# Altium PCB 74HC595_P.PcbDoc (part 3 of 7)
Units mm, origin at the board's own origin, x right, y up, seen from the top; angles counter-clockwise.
Board outline 89.11 x 89.03 mm, 2 copper layers (Top Layer, Bottom Layer); 552 components, 23 nets, 1488 pads, 408 vias.
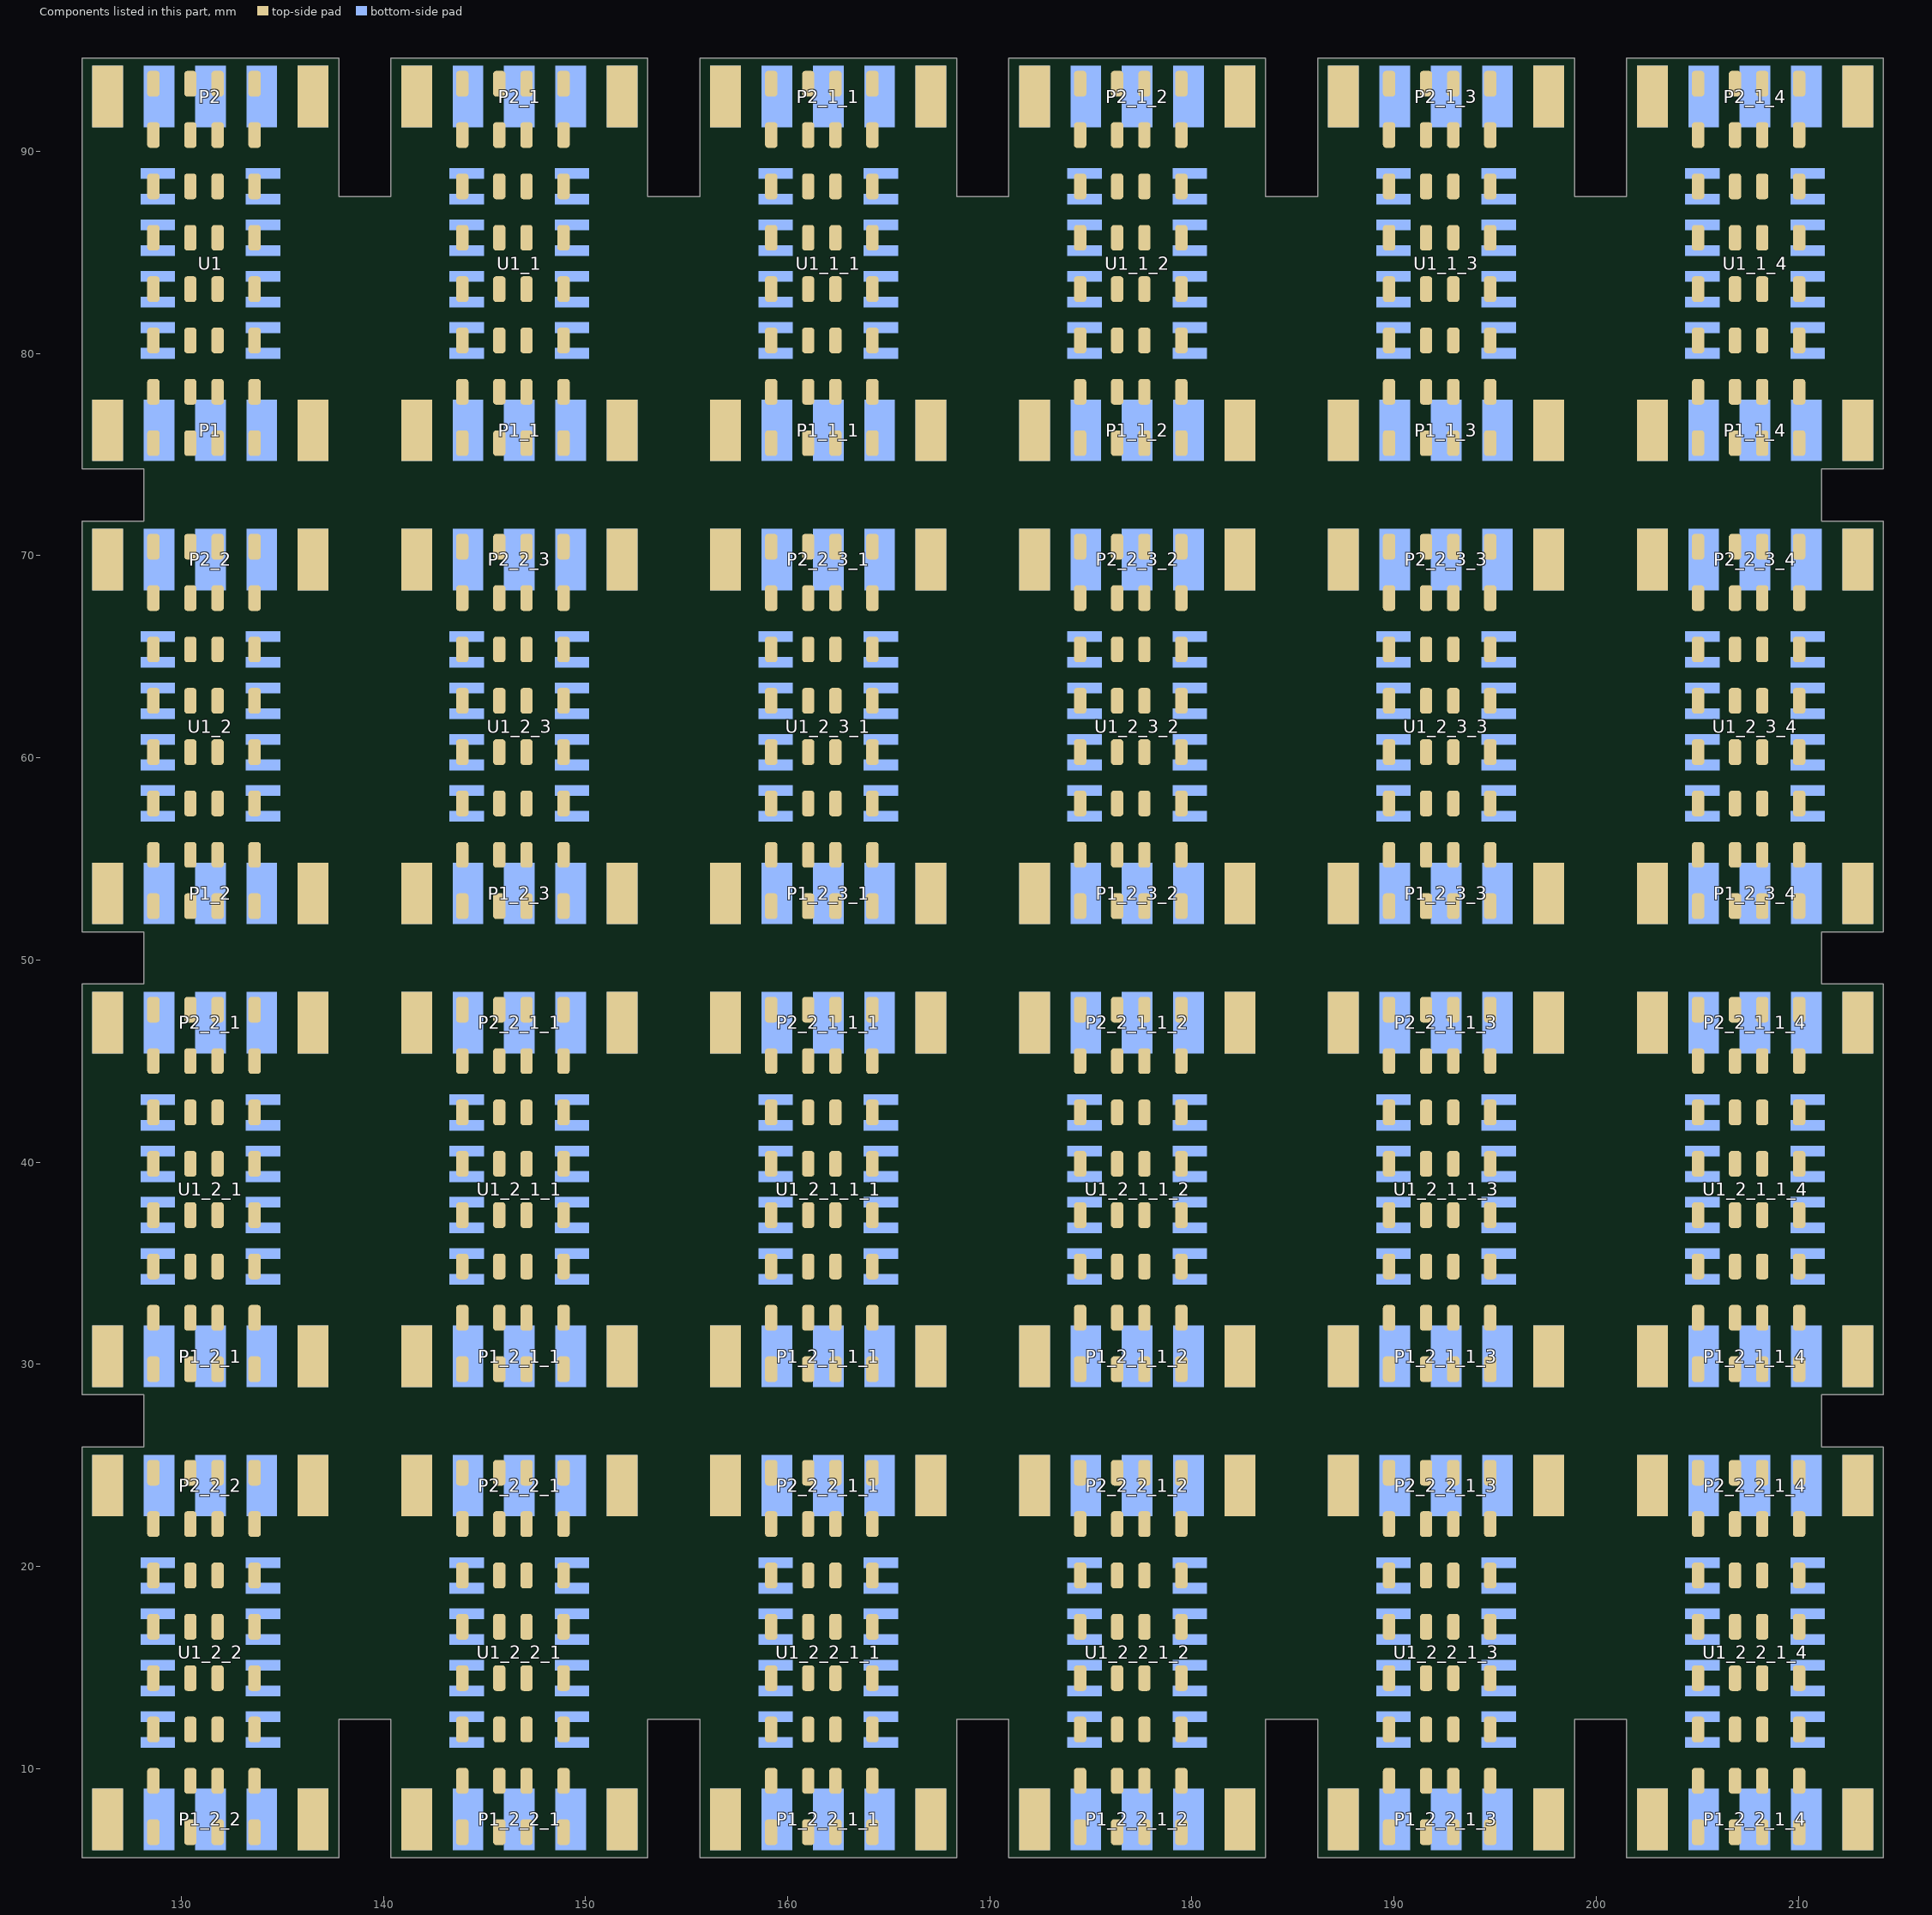
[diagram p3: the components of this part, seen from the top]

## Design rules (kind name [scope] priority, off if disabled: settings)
Clearance [All] p1: gap=0.254
PolygonConnect [All] p1: connectstyle=Relief reliefconductorwidth=0.254 reliefentries=4 polygonreliefangle="90 Angle" airgapwidth=0.254
RoutingVias [All] p1: holewidth=0.381 width=0.635 viastyle="Through Hole" minholewidth=0.254 minwidth=0.381 maxholewidth=1.27 maxwidth=1.524
SolderMaskExpansion [All] p1: expansion=0.102
Width [All] p1: maxlimit=1.27 minlimit=0.254 preferedwidth=0.381
30 further rules are at their usual default settings.

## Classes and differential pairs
component class EspPov: D1 D2 D3 D4 D5 D6 D7 D8 P1 P2 P3 P4 P5 P6 R1 R2 R3 R4 R5 R6 R7 R8 U1

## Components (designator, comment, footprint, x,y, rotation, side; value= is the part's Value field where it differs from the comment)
D1 "color?" LED_0805_RED 132.715,75.565 r180 top
D1_1 "color?" LED_0805_RED 147.997,75.565 r180 top (schematic designator D1)
D1_1_1 "color?" LED_0805_RED 163.279,75.565 r180 top (schematic designator D1)
D1_1_2 "color?" LED_0805_RED 178.561,75.565 r180 top (schematic designator D1)
D1_1_3 "color?" LED_0805_RED 193.843,75.565 r180 top (schematic designator D1)
D1_1_4 "color?" LED_0805_RED 209.125,75.565 r180 top (schematic designator D1)
D1_2 "color?" LED_0805_RED 132.715,52.663 r180 top (schematic designator D1)
D1_2_1 "color?" LED_0805_RED 132.715,29.761 r180 top (schematic designator D1)
D1_2_1_1 "color?" LED_0805_RED 147.997,29.761 r180 top (schematic designator D1)
D1_2_1_1_1 "color?" LED_0805_RED 163.279,29.761 r180 top (schematic designator D1)
D1_2_1_1_2 "color?" LED_0805_RED 178.561,29.761 r180 top (schematic designator D1)
D1_2_1_1_3 "color?" LED_0805_RED 193.843,29.761 r180 top (schematic designator D1)
D1_2_1_1_4 "color?" LED_0805_RED 209.125,29.761 r180 top (schematic designator D1)
D1_2_2 "color?" LED_0805_RED 132.715,6.859 r180 top (schematic designator D1)
D1_2_2_1 "color?" LED_0805_RED 147.997,6.859 r180 top (schematic designator D1)
D1_2_2_1_1 "color?" LED_0805_RED 163.279,6.859 r180 top (schematic designator D1)
D1_2_2_1_2 "color?" LED_0805_RED 178.561,6.859 r180 top (schematic designator D1)
D1_2_2_1_3 "color?" LED_0805_RED 193.843,6.859 r180 top (schematic designator D1)
D1_2_2_1_4 "color?" LED_0805_RED 209.125,6.859 r180 top (schematic designator D1)
D1_2_3 "color?" LED_0805_RED 147.997,52.663 r180 top (schematic designator D1)
D1_2_3_1 "color?" LED_0805_RED 163.279,52.663 r180 top (schematic designator D1)
D1_2_3_2 "color?" LED_0805_RED 178.561,52.663 r180 top (schematic designator D1)
D1_2_3_3 "color?" LED_0805_RED 193.843,52.663 r180 top (schematic designator D1)
D1_2_3_4 "color?" LED_0805_RED 209.125,52.663 r180 top (schematic designator D1)
D2 "color?" LED_0805_RED 132.715,78.105 r180 top
D2_1 "color?" LED_0805_RED 147.997,78.105 r180 top (schematic designator D2)
D2_1_1 "color?" LED_0805_RED 163.279,78.105 r180 top (schematic designator D2)
D2_1_2 "color?" LED_0805_RED 178.561,78.105 r180 top (schematic designator D2)
D2_1_3 "color?" LED_0805_RED 193.843,78.105 r180 top (schematic designator D2)
D2_1_4 "color?" LED_0805_RED 209.125,78.105 r180 top (schematic designator D2)
D2_2 "color?" LED_0805_RED 132.715,55.203 r180 top (schematic designator D2)
D2_2_1 "color?" LED_0805_RED 132.715,32.301 r180 top (schematic designator D2)
D2_2_1_1 "color?" LED_0805_RED 147.997,32.301 r180 top (schematic designator D2)
D2_2_1_1_1 "color?" LED_0805_RED 163.279,32.301 r180 top (schematic designator D2)
D2_2_1_1_2 "color?" LED_0805_RED 178.561,32.301 r180 top (schematic designator D2)
D2_2_1_1_3 "color?" LED_0805_RED 193.843,32.301 r180 top (schematic designator D2)
D2_2_1_1_4 "color?" LED_0805_RED 209.125,32.301 r180 top (schematic designator D2)
D2_2_2 "color?" LED_0805_RED 132.715,9.399 r180 top (schematic designator D2)
D2_2_2_1 "color?" LED_0805_RED 147.997,9.399 r180 top (schematic designator D2)
D2_2_2_1_1 "color?" LED_0805_RED 163.279,9.399 r180 top (schematic designator D2)
D2_2_2_1_2 "color?" LED_0805_RED 178.561,9.399 r180 top (schematic designator D2)
D2_2_2_1_3 "color?" LED_0805_RED 193.843,9.399 r180 top (schematic designator D2)
D2_2_2_1_4 "color?" LED_0805_RED 209.125,9.399 r180 top (schematic designator D2)
D2_2_3 "color?" LED_0805_RED 147.997,55.203 r180 top (schematic designator D2)
D2_2_3_1 "color?" LED_0805_RED 163.279,55.203 r180 top (schematic designator D2)
D2_2_3_2 "color?" LED_0805_RED 178.561,55.203 r180 top (schematic designator D2)
D2_2_3_3 "color?" LED_0805_RED 193.843,55.203 r180 top (schematic designator D2)
D2_2_3_4 "color?" LED_0805_RED 209.125,55.203 r180 top (schematic designator D2)
D3 "color?" LED_0805_RED 132.715,80.645 r180 top
D3_1 "color?" LED_0805_RED 147.997,80.645 r180 top (schematic designator D3)
D3_1_1 "color?" LED_0805_RED 163.279,80.645 r180 top (schematic designator D3)
D3_1_2 "color?" LED_0805_RED 178.561,80.645 r180 top (schematic designator D3)
D3_1_3 "color?" LED_0805_RED 193.843,80.645 r180 top (schematic designator D3)
D3_1_4 "color?" LED_0805_RED 209.125,80.645 r180 top (schematic designator D3)
D3_2 "color?" LED_0805_RED 132.715,57.743 r180 top (schematic designator D3)
D3_2_1 "color?" LED_0805_RED 132.715,34.841 r180 top (schematic designator D3)
D3_2_1_1 "color?" LED_0805_RED 147.997,34.841 r180 top (schematic designator D3)
D3_2_1_1_1 "color?" LED_0805_RED 163.279,34.841 r180 top (schematic designator D3)
D3_2_1_1_2 "color?" LED_0805_RED 178.561,34.841 r180 top (schematic designator D3)
D3_2_1_1_3 "color?" LED_0805_RED 193.843,34.841 r180 top (schematic designator D3)
D3_2_1_1_4 "color?" LED_0805_RED 209.125,34.841 r180 top (schematic designator D3)
D3_2_2 "color?" LED_0805_RED 132.715,11.939 r180 top (schematic designator D3)
D3_2_2_1 "color?" LED_0805_RED 147.997,11.939 r180 top (schematic designator D3)
D3_2_2_1_1 "color?" LED_0805_RED 163.279,11.939 r180 top (schematic designator D3)
D3_2_2_1_2 "color?" LED_0805_RED 178.561,11.939 r180 top (schematic designator D3)
D3_2_2_1_3 "color?" LED_0805_RED 193.843,11.939 r180 top (schematic designator D3)
D3_2_2_1_4 "color?" LED_0805_RED 209.125,11.939 r180 top (schematic designator D3)
D3_2_3 "color?" LED_0805_RED 147.997,57.743 r180 top (schematic designator D3)
D3_2_3_1 "color?" LED_0805_RED 163.279,57.743 r180 top (schematic designator D3)
D3_2_3_2 "color?" LED_0805_RED 178.561,57.743 r180 top (schematic designator D3)
D3_2_3_3 "color?" LED_0805_RED 193.843,57.743 r180 top (schematic designator D3)
D3_2_3_4 "color?" LED_0805_RED 209.125,57.743 r180 top (schematic designator D3)
D4 "color?" LED_0805_RED 132.715,83.185 r180 top
D4_1 "color?" LED_0805_RED 147.997,83.185 r180 top (schematic designator D4)
D4_1_1 "color?" LED_0805_RED 163.279,83.185 r180 top (schematic designator D4)
D4_1_2 "color?" LED_0805_RED 178.561,83.185 r180 top (schematic designator D4)
D4_1_3 "color?" LED_0805_RED 193.843,83.185 r180 top (schematic designator D4)
D4_1_4 "color?" LED_0805_RED 209.125,83.185 r180 top (schematic designator D4)
D4_2 "color?" LED_0805_RED 132.715,60.283 r180 top (schematic designator D4)
D4_2_1 "color?" LED_0805_RED 132.715,37.381 r180 top (schematic designator D4)
D4_2_1_1 "color?" LED_0805_RED 147.997,37.381 r180 top (schematic designator D4)
D4_2_1_1_1 "color?" LED_0805_RED 163.279,37.381 r180 top (schematic designator D4)
D4_2_1_1_2 "color?" LED_0805_RED 178.561,37.381 r180 top (schematic designator D4)
D4_2_1_1_3 "color?" LED_0805_RED 193.843,37.381 r180 top (schematic designator D4)
D4_2_1_1_4 "color?" LED_0805_RED 209.125,37.381 r180 top (schematic designator D4)
D4_2_2 "color?" LED_0805_RED 132.715,14.479 r180 top (schematic designator D4)
D4_2_2_1 "color?" LED_0805_RED 147.997,14.479 r180 top (schematic designator D4)
D4_2_2_1_1 "color?" LED_0805_RED 163.279,14.479 r180 top (schematic designator D4)
D4_2_2_1_2 "color?" LED_0805_RED 178.561,14.479 r180 top (schematic designator D4)
D4_2_2_1_3 "color?" LED_0805_RED 193.843,14.479 r180 top (schematic designator D4)
D4_2_2_1_4 "color?" LED_0805_RED 209.125,14.479 r180 top (schematic designator D4)
D4_2_3 "color?" LED_0805_RED 147.997,60.283 r180 top (schematic designator D4)
D4_2_3_1 "color?" LED_0805_RED 163.279,60.283 r180 top (schematic designator D4)
D4_2_3_2 "color?" LED_0805_RED 178.561,60.283 r180 top (schematic designator D4)
D4_2_3_3 "color?" LED_0805_RED 193.843,60.283 r180 top (schematic designator D4)
D4_2_3_4 "color?" LED_0805_RED 209.125,60.283 r180 top (schematic designator D4)
D5 "color?" LED_0805_RED 132.715,85.725 r180 top
D5_1 "color?" LED_0805_RED 147.997,85.725 r180 top (schematic designator D5)
D5_1_1 "color?" LED_0805_RED 163.279,85.725 r180 top (schematic designator D5)
D5_1_2 "color?" LED_0805_RED 178.561,85.725 r180 top (schematic designator D5)
D5_1_3 "color?" LED_0805_RED 193.843,85.725 r180 top (schematic designator D5)
D5_1_4 "color?" LED_0805_RED 209.125,85.725 r180 top (schematic designator D5)
D5_2 "color?" LED_0805_RED 132.715,62.823 r180 top (schematic designator D5)
D5_2_1 "color?" LED_0805_RED 132.715,39.921 r180 top (schematic designator D5)
D5_2_1_1 "color?" LED_0805_RED 147.997,39.921 r180 top (schematic designator D5)
D5_2_1_1_1 "color?" LED_0805_RED 163.279,39.921 r180 top (schematic designator D5)
D5_2_1_1_2 "color?" LED_0805_RED 178.561,39.921 r180 top (schematic designator D5)
D5_2_1_1_3 "color?" LED_0805_RED 193.843,39.921 r180 top (schematic designator D5)
D5_2_1_1_4 "color?" LED_0805_RED 209.125,39.921 r180 top (schematic designator D5)
D5_2_2 "color?" LED_0805_RED 132.715,17.019 r180 top (schematic designator D5)
D5_2_2_1 "color?" LED_0805_RED 147.997,17.019 r180 top (schematic designator D5)
D5_2_2_1_1 "color?" LED_0805_RED 163.279,17.019 r180 top (schematic designator D5)
D5_2_2_1_2 "color?" LED_0805_RED 178.561,17.019 r180 top (schematic designator D5)
D5_2_2_1_3 "color?" LED_0805_RED 193.843,17.019 r180 top (schematic designator D5)
D5_2_2_1_4 "color?" LED_0805_RED 209.125,17.019 r180 top (schematic designator D5)
D5_2_3 "color?" LED_0805_RED 147.997,62.823 r180 top (schematic designator D5)
D5_2_3_1 "color?" LED_0805_RED 163.279,62.823 r180 top (schematic designator D5)
D5_2_3_2 "color?" LED_0805_RED 178.561,62.823 r180 top (schematic designator D5)
D5_2_3_3 "color?" LED_0805_RED 193.843,62.823 r180 top (schematic designator D5)
D5_2_3_4 "color?" LED_0805_RED 209.125,62.823 r180 top (schematic designator D5)
D6 "color?" LED_0805_RED 132.715,88.265 r180 top
D6_1 "color?" LED_0805_RED 147.997,88.265 r180 top (schematic designator D6)
D6_1_1 "color?" LED_0805_RED 163.279,88.265 r180 top (schematic designator D6)
D6_1_2 "color?" LED_0805_RED 178.561,88.265 r180 top (schematic designator D6)
D6_1_3 "color?" LED_0805_RED 193.843,88.265 r180 top (schematic designator D6)
D6_1_4 "color?" LED_0805_RED 209.125,88.265 r180 top (schematic designator D6)
D6_2 "color?" LED_0805_RED 132.715,65.363 r180 top (schematic designator D6)
D6_2_1 "color?" LED_0805_RED 132.715,42.461 r180 top (schematic designator D6)
D6_2_1_1 "color?" LED_0805_RED 147.997,42.461 r180 top (schematic designator D6)
D6_2_1_1_1 "color?" LED_0805_RED 163.279,42.461 r180 top (schematic designator D6)
D6_2_1_1_2 "color?" LED_0805_RED 178.561,42.461 r180 top (schematic designator D6)
D6_2_1_1_3 "color?" LED_0805_RED 193.843,42.461 r180 top (schematic designator D6)
D6_2_1_1_4 "color?" LED_0805_RED 209.125,42.461 r180 top (schematic designator D6)
D6_2_2 "color?" LED_0805_RED 132.715,19.559 r180 top (schematic designator D6)
D6_2_2_1 "color?" LED_0805_RED 147.997,19.559 r180 top (schematic designator D6)
D6_2_2_1_1 "color?" LED_0805_RED 163.279,19.559 r180 top (schematic designator D6)
D6_2_2_1_2 "color?" LED_0805_RED 178.561,19.559 r180 top (schematic designator D6)
D6_2_2_1_3 "color?" LED_0805_RED 193.843,19.559 r180 top (schematic designator D6)
D6_2_2_1_4 "color?" LED_0805_RED 209.125,19.559 r180 top (schematic designator D6)
D6_2_3 "color?" LED_0805_RED 147.997,65.363 r180 top (schematic designator D6)
D6_2_3_1 "color?" LED_0805_RED 163.279,65.363 r180 top (schematic designator D6)
D6_2_3_2 "color?" LED_0805_RED 178.561,65.363 r180 top (schematic designator D6)
D6_2_3_3 "color?" LED_0805_RED 193.843,65.363 r180 top (schematic designator D6)
D6_2_3_4 "color?" LED_0805_RED 209.125,65.363 r180 top (schematic designator D6)
D7 "color?" LED_0805_RED 132.715,90.805 r180 top
D7_1 "color?" LED_0805_RED 147.997,90.805 r180 top (schematic designator D7)
D7_1_1 "color?" LED_0805_RED 163.279,90.805 r180 top (schematic designator D7)
D7_1_2 "color?" LED_0805_RED 178.561,90.805 r180 top (schematic designator D7)
D7_1_3 "color?" LED_0805_RED 193.843,90.805 r180 top (schematic designator D7)
D7_1_4 "color?" LED_0805_RED 209.125,90.805 r180 top (schematic designator D7)
D7_2 "color?" LED_0805_RED 132.715,67.903 r180 top (schematic designator D7)
D7_2_1 "color?" LED_0805_RED 132.715,45.001 r180 top (schematic designator D7)
D7_2_1_1 "color?" LED_0805_RED 147.997,45.001 r180 top (schematic designator D7)
D7_2_1_1_1 "color?" LED_0805_RED 163.279,45.001 r180 top (schematic designator D7)
D7_2_1_1_2 "color?" LED_0805_RED 178.561,45.001 r180 top (schematic designator D7)
D7_2_1_1_3 "color?" LED_0805_RED 193.843,45.001 r180 top (schematic designator D7)
D7_2_1_1_4 "color?" LED_0805_RED 209.125,45.001 r180 top (schematic designator D7)
D7_2_2 "color?" LED_0805_RED 132.715,22.099 r180 top (schematic designator D7)
D7_2_2_1 "color?" LED_0805_RED 147.997,22.099 r180 top (schematic designator D7)
D7_2_2_1_1 "color?" LED_0805_RED 163.279,22.099 r180 top (schematic designator D7)
D7_2_2_1_2 "color?" LED_0805_RED 178.561,22.099 r180 top (schematic designator D7)
D7_2_2_1_3 "color?" LED_0805_RED 193.843,22.099 r180 top (schematic designator D7)
D7_2_2_1_4 "color?" LED_0805_RED 209.125,22.099 r180 top (schematic designator D7)
D7_2_3 "color?" LED_0805_RED 147.997,67.903 r180 top (schematic designator D7)
D7_2_3_1 "color?" LED_0805_RED 163.279,67.903 r180 top (schematic designator D7)
D7_2_3_2 "color?" LED_0805_RED 178.561,67.903 r180 top (schematic designator D7)
D7_2_3_3 "color?" LED_0805_RED 193.843,67.903 r180 top (schematic designator D7)
D7_2_3_4 "color?" LED_0805_RED 209.125,67.903 r180 top (schematic designator D7)
D8 "color?" LED_0805_RED 132.715,93.345 r180 top
D8_1 "color?" LED_0805_RED 147.997,93.345 r180 top (schematic designator D8)
D8_1_1 "color?" LED_0805_RED 163.279,93.345 r180 top (schematic designator D8)
D8_1_2 "color?" LED_0805_RED 178.561,93.345 r180 top (schematic designator D8)
D8_1_3 "color?" LED_0805_RED 193.843,93.345 r180 top (schematic designator D8)
D8_1_4 "color?" LED_0805_RED 209.125,93.345 r180 top (schematic designator D8)
D8_2 "color?" LED_0805_RED 132.715,70.443 r180 top (schematic designator D8)
D8_2_1 "color?" LED_0805_RED 132.715,47.541 r180 top (schematic designator D8)
D8_2_1_1 "color?" LED_0805_RED 147.997,47.541 r180 top (schematic designator D8)
D8_2_1_1_1 "color?" LED_0805_RED 163.279,47.541 r180 top (schematic designator D8)
D8_2_1_1_2 "color?" LED_0805_RED 178.561,47.541 r180 top (schematic designator D8)
D8_2_1_1_3 "color?" LED_0805_RED 193.843,47.541 r180 top (schematic designator D8)
D8_2_1_1_4 "color?" LED_0805_RED 209.125,47.541 r180 top (schematic designator D8)
D8_2_2 "color?" LED_0805_RED 132.715,24.639 r180 top (schematic designator D8)
D8_2_2_1 "color?" LED_0805_RED 147.997,24.639 r180 top (schematic designator D8)
D8_2_2_1_1 "color?" LED_0805_RED 163.279,24.639 r180 top (schematic designator D8)
D8_2_2_1_2 "color?" LED_0805_RED 178.561,24.639 r180 top (schematic designator D8)
D8_2_2_1_3 "color?" LED_0805_RED 193.843,24.639 r180 top (schematic designator D8)
D8_2_2_1_4 "color?" LED_0805_RED 209.125,24.639 r180 top (schematic designator D8)
D8_2_3 "color?" LED_0805_RED 147.997,70.443 r180 top (schematic designator D8)
D8_2_3_1 "color?" LED_0805_RED 163.279,70.443 r180 top (schematic designator D8)
D8_2_3_2 "color?" LED_0805_RED 178.561,70.443 r180 top (schematic designator D8)
D8_2_3_3 "color?" LED_0805_RED 193.843,70.443 r180 top (schematic designator D8)
D8_2_3_4 "color?" LED_0805_RED 209.125,70.443 r180 top (schematic designator D8)
P1 "Header 5" HDR1X5_SOP 126.365,76.2 r0 bottom
P1_1 "Header 5" HDR1X5_SOP 141.647,76.2 r0 bottom (schematic designator P1)
P1_1_1 "Header 5" HDR1X5_SOP 156.929,76.2 r0 bottom (schematic designator P1)
P1_1_2 "Header 5" HDR1X5_SOP 172.211,76.2 r0 bottom (schematic designator P1)
P1_1_3 "Header 5" HDR1X5_SOP 187.493,76.2 r0 bottom (schematic designator P1)
P1_1_4 "Header 5" HDR1X5_SOP 202.775,76.2 r0 bottom (schematic designator P1)
P1_2 "Header 5" HDR1X5_SOP 126.365,53.298 r0 bottom (schematic designator P1)
P1_2_1 "Header 5" HDR1X5_SOP 126.365,30.396 r0 bottom (schematic designator P1)
P1_2_1_1 "Header 5" HDR1X5_SOP 141.647,30.396 r0 bottom (schematic designator P1)
P1_2_1_1_1 "Header 5" HDR1X5_SOP 156.929,30.396 r0 bottom (schematic designator P1)
P1_2_1_1_2 "Header 5" HDR1X5_SOP 172.211,30.396 r0 bottom (schematic designator P1)
P1_2_1_1_3 "Header 5" HDR1X5_SOP 187.493,30.396 r0 bottom (schematic designator P1)
P1_2_1_1_4 "Header 5" HDR1X5_SOP 202.775,30.396 r0 bottom (schematic designator P1)
P1_2_2 "Header 5" HDR1X5_SOP 126.365,7.494 r0 bottom (schematic designator P1)
P1_2_2_1 "Header 5" HDR1X5_SOP 141.647,7.494 r0 bottom (schematic designator P1)
P1_2_2_1_1 "Header 5" HDR1X5_SOP 156.929,7.494 r0 bottom (schematic designator P1)
P1_2_2_1_2 "Header 5" HDR1X5_SOP 172.211,7.494 r0 bottom (schematic designator P1)
P1_2_2_1_3 "Header 5" HDR1X5_SOP 187.493,7.494 r0 bottom (schematic designator P1)
P1_2_2_1_4 "Header 5" HDR1X5_SOP 202.775,7.494 r0 bottom (schematic designator P1)
P1_2_3 "Header 5" HDR1X5_SOP 141.647,53.298 r0 bottom (schematic designator P1)
P1_2_3_1 "Header 5" HDR1X5_SOP 156.929,53.298 r0 bottom (schematic designator P1)
P1_2_3_2 "Header 5" HDR1X5_SOP 172.211,53.298 r0 bottom (schematic designator P1)
P1_2_3_3 "Header 5" HDR1X5_SOP 187.493,53.298 r0 bottom (schematic designator P1)
P1_2_3_4 "Header 5" HDR1X5_SOP 202.775,53.298 r0 bottom (schematic designator P1)
P2 "Header 5" HDR1X5_SOP 126.365,92.71 r0 bottom
P2_1 "Header 5" HDR1X5_SOP 141.647,92.71 r0 bottom (schematic designator P2)
P2_1_1 "Header 5" HDR1X5_SOP 156.929,92.71 r0 bottom (schematic designator P2)
P2_1_2 "Header 5" HDR1X5_SOP 172.211,92.71 r0 bottom (schematic designator P2)
P2_1_3 "Header 5" HDR1X5_SOP 187.493,92.71 r0 bottom (schematic designator P2)
P2_1_4 "Header 5" HDR1X5_SOP 202.775,92.71 r0 bottom (schematic designator P2)
P2_2 "Header 5" HDR1X5_SOP 126.365,69.808 r0 bottom (schematic designator P2)
P2_2_1 "Header 5" HDR1X5_SOP 126.365,46.906 r0 bottom (schematic designator P2)
P2_2_1_1 "Header 5" HDR1X5_SOP 141.647,46.906 r0 bottom (schematic designator P2)
P2_2_1_1_1 "Header 5" HDR1X5_SOP 156.929,46.906 r0 bottom (schematic designator P2)
P2_2_1_1_2 "Header 5" HDR1X5_SOP 172.211,46.906 r0 bottom (schematic designator P2)
P2_2_1_1_3 "Header 5" HDR1X5_SOP 187.493,46.906 r0 bottom (schematic designator P2)
P2_2_1_1_4 "Header 5" HDR1X5_SOP 202.775,46.906 r0 bottom (schematic designator P2)
P2_2_2 "Header 5" HDR1X5_SOP 126.365,24.004 r0 bottom (schematic designator P2)
P2_2_2_1 "Header 5" HDR1X5_SOP 141.647,24.004 r0 bottom (schematic designator P2)
P2_2_2_1_1 "Header 5" HDR1X5_SOP 156.929,24.004 r0 bottom (schematic designator P2)
P2_2_2_1_2 "Header 5" HDR1X5_SOP 172.211,24.004 r0 bottom (schematic designator P2)
P2_2_2_1_3 "Header 5" HDR1X5_SOP 187.493,24.004 r0 bottom (schematic designator P2)
P2_2_2_1_4 "Header 5" HDR1X5_SOP 202.775,24.004 r0 bottom (schematic designator P2)
P2_2_3 "Header 5" HDR1X5_SOP 141.647,69.808 r0 bottom (schematic designator P2)
P2_2_3_1 "Header 5" HDR1X5_SOP 156.929,69.808 r0 bottom (schematic designator P2)
P2_2_3_2 "Header 5" HDR1X5_SOP 172.211,69.808 r0 bottom (schematic designator P2)
P2_2_3_3 "Header 5" HDR1X5_SOP 187.493,69.808 r0 bottom (schematic designator P2)
P2_2_3_4 "Header 5" HDR1X5_SOP 202.775,69.808 r0 bottom (schematic designator P2)
P3 "Header 1" HDR1X1_SOP 126.365,76.2 r0 top
P3_1 "Header 1" HDR1X1_SOP 141.647,76.2 r0 top (schematic designator P3)
P3_1_1 "Header 1" HDR1X1_SOP 156.929,76.2 r0 top (schematic designator P3)
P3_1_2 "Header 1" HDR1X1_SOP 172.211,76.2 r0 top (schematic designator P3)
P3_1_3 "Header 1" HDR1X1_SOP 187.493,76.2 r0 top (schematic designator P3)
P3_1_4 "Header 1" HDR1X1_SOP 202.775,76.2 r0 top (schematic designator P3)
P3_2 "Header 1" HDR1X1_SOP 126.365,53.298 r0 top (schematic designator P3)
P3_2_1 "Header 1" HDR1X1_SOP 126.365,30.396 r0 top (schematic designator P3)
P3_2_1_1 "Header 1" HDR1X1_SOP 141.647,30.396 r0 top (schematic designator P3)
P3_2_1_1_1 "Header 1" HDR1X1_SOP 156.929,30.396 r0 top (schematic designator P3)
P3_2_1_1_2 "Header 1" HDR1X1_SOP 172.211,30.396 r0 top (schematic designator P3)
P3_2_1_1_3 "Header 1" HDR1X1_SOP 187.493,30.396 r0 top (schematic designator P3)
P3_2_1_1_4 "Header 1" HDR1X1_SOP 202.775,30.396 r0 top (schematic designator P3)
P3_2_2 "Header 1" HDR1X1_SOP 126.365,7.494 r0 top (schematic designator P3)
P3_2_2_1 "Header 1" HDR1X1_SOP 141.647,7.494 r0 top (schematic designator P3)
P3_2_2_1_1 "Header 1" HDR1X1_SOP 156.929,7.494 r0 top (schematic designator P3)
P3_2_2_1_2 "Header 1" HDR1X1_SOP 172.211,7.494 r0 top (schematic designator P3)
P3_2_2_1_3 "Header 1" HDR1X1_SOP 187.493,7.494 r0 top (schematic designator P3)
P3_2_2_1_4 "Header 1" HDR1X1_SOP 202.775,7.494 r0 top (schematic designator P3)
P3_2_3 "Header 1" HDR1X1_SOP 141.647,53.298 r0 top (schematic designator P3)
P3_2_3_1 "Header 1" HDR1X1_SOP 156.929,53.298 r0 top (schematic designator P3)
P3_2_3_2 "Header 1" HDR1X1_SOP 172.211,53.298 r0 top (schematic designator P3)
P3_2_3_3 "Header 1" HDR1X1_SOP 187.493,53.298 r0 top (schematic designator P3)
P3_2_3_4 "Header 1" HDR1X1_SOP 202.775,53.298 r0 top (schematic designator P3)
P4 "Header 1" HDR1X1_SOP 136.525,92.71 r0 top
P4_1 "Header 1" HDR1X1_SOP 151.807,92.71 r0 top (schematic designator P4)
P4_1_1 "Header 1" HDR1X1_SOP 167.089,92.71 r0 top (schematic designator P4)
P4_1_2 "Header 1" HDR1X1_SOP 182.371,92.71 r0 top (schematic designator P4)
P4_1_3 "Header 1" HDR1X1_SOP 197.653,92.71 r0 top (schematic designator P4)
P4_1_4 "Header 1" HDR1X1_SOP 212.935,92.71 r0 top (schematic designator P4)
P4_2 "Header 1" HDR1X1_SOP 136.525,69.808 r0 top (schematic designator P4)
P4_2_1 "Header 1" HDR1X1_SOP 136.525,46.906 r0 top (schematic designator P4)
P4_2_1_1 "Header 1" HDR1X1_SOP 151.807,46.906 r0 top (schematic designator P4)
P4_2_1_1_1 "Header 1" HDR1X1_SOP 167.089,46.906 r0 top (schematic designator P4)
P4_2_1_1_2 "Header 1" HDR1X1_SOP 182.371,46.906 r0 top (schematic designator P4)
P4_2_1_1_3 "Header 1" HDR1X1_SOP 197.653,46.906 r0 top (schematic designator P4)
P4_2_1_1_4 "Header 1" HDR1X1_SOP 212.935,46.906 r0 top (schematic designator P4)
P4_2_2 "Header 1" HDR1X1_SOP 136.525,24.004 r0 top (schematic designator P4)
P4_2_2_1 "Header 1" HDR1X1_SOP 151.807,24.004 r0 top (schematic designator P4)
P4_2_2_1_1 "Header 1" HDR1X1_SOP 167.089,24.004 r0 top (schematic designator P4)
P4_2_2_1_2 "Header 1" HDR1X1_SOP 182.371,24.004 r0 top (schematic designator P4)
P4_2_2_1_3 "Header 1" HDR1X1_SOP 197.653,24.004 r0 top (schematic designator P4)
P4_2_2_1_4 "Header 1" HDR1X1_SOP 212.935,24.004 r0 top (schematic designator P4)
P4_2_3 "Header 1" HDR1X1_SOP 151.807,69.808 r0 top (schematic designator P4)
P4_2_3_1 "Header 1" HDR1X1_SOP 167.089,69.808 r0 top (schematic designator P4)
P4_2_3_2 "Header 1" HDR1X1_SOP 182.371,69.808 r0 top (schematic designator P4)
P4_2_3_3 "Header 1" HDR1X1_SOP 197.653,69.808 r0 top (schematic designator P4)
P4_2_3_4 "Header 1" HDR1X1_SOP 212.935,69.808 r0 top (schematic designator P4)
P5 "Header 1" HDR1X1_SOP 126.365,92.71 r0 top
P5_1 "Header 1" HDR1X1_SOP 141.647,92.71 r0 top (schematic designator P5)
P5_1_1 "Header 1" HDR1X1_SOP 156.929,92.71 r0 top (schematic designator P5)
P5_1_2 "Header 1" HDR1X1_SOP 172.211,92.71 r0 top (schematic designator P5)
P5_1_3 "Header 1" HDR1X1_SOP 187.493,92.71 r0 top (schematic designator P5)
P5_1_4 "Header 1" HDR1X1_SOP 202.775,92.71 r0 top (schematic designator P5)
P5_2 "Header 1" HDR1X1_SOP 126.365,69.808 r0 top (schematic designator P5)
P5_2_1 "Header 1" HDR1X1_SOP 126.365,46.906 r0 top (schematic designator P5)
P5_2_1_1 "Header 1" HDR1X1_SOP 141.647,46.906 r0 top (schematic designator P5)
P5_2_1_1_1 "Header 1" HDR1X1_SOP 156.929,46.906 r0 top (schematic designator P5)
P5_2_1_1_2 "Header 1" HDR1X1_SOP 172.211,46.906 r0 top (schematic designator P5)
P5_2_1_1_3 "Header 1" HDR1X1_SOP 187.493,46.906 r0 top (schematic designator P5)
P5_2_1_1_4 "Header 1" HDR1X1_SOP 202.775,46.906 r0 top (schematic designator P5)
P5_2_2 "Header 1" HDR1X1_SOP 126.365,24.004 r0 top (schematic designator P5)
P5_2_2_1 "Header 1" HDR1X1_SOP 141.647,24.004 r0 top (schematic designator P5)
P5_2_2_1_1 "Header 1" HDR1X1_SOP 156.929,24.004 r0 top (schematic designator P5)
P5_2_2_1_2 "Header 1" HDR1X1_SOP 172.211,24.004 r0 top (schematic designator P5)
P5_2_2_1_3 "Header 1" HDR1X1_SOP 187.493,24.004 r0 top (schematic designator P5)
P5_2_2_1_4 "Header 1" HDR1X1_SOP 202.775,24.004 r0 top (schematic designator P5)
P5_2_3 "Header 1" HDR1X1_SOP 141.647,69.808 r0 top (schematic designator P5)
P5_2_3_1 "Header 1" HDR1X1_SOP 156.929,69.808 r0 top (schematic designator P5)
P5_2_3_2 "Header 1" HDR1X1_SOP 172.211,69.808 r0 top (schematic designator P5)
P5_2_3_3 "Header 1" HDR1X1_SOP 187.493,69.808 r0 top (schematic designator P5)
P5_2_3_4 "Header 1" HDR1X1_SOP 202.775,69.808 r0 top (schematic designator P5)
P6 "Header 1" HDR1X1_SOP 136.525,76.2 r0 top
P6_1 "Header 1" HDR1X1_SOP 151.807,76.2 r0 top (schematic designator P6)
P6_1_1 "Header 1" HDR1X1_SOP 167.089,76.2 r0 top (schematic designator P6)
P6_1_2 "Header 1" HDR1X1_SOP 182.371,76.2 r0 top (schematic designator P6)
P6_1_3 "Header 1" HDR1X1_SOP 197.653,76.2 r0 top (schematic designator P6)
P6_1_4 "Header 1" HDR1X1_SOP 212.935,76.2 r0 top (schematic designator P6)
P6_2 "Header 1" HDR1X1_SOP 136.525,53.298 r0 top (schematic designator P6)
P6_2_1 "Header 1" HDR1X1_SOP 136.525,30.396 r0 top (schematic designator P6)
P6_2_1_1 "Header 1" HDR1X1_SOP 151.807,30.396 r0 top (schematic designator P6)
P6_2_1_1_1 "Header 1" HDR1X1_SOP 167.089,30.396 r0 top (schematic designator P6)
P6_2_1_1_2 "Header 1" HDR1X1_SOP 182.371,30.396 r0 top (schematic designator P6)
P6_2_1_1_3 "Header 1" HDR1X1_SOP 197.653,30.396 r0 top (schematic designator P6)
P6_2_1_1_4 "Header 1" HDR1X1_SOP 212.935,30.396 r0 top (schematic designator P6)
P6_2_2 "Header 1" HDR1X1_SOP 136.525,7.494 r0 top (schematic designator P6)
P6_2_2_1 "Header 1" HDR1X1_SOP 151.807,7.494 r0 top (schematic designator P6)
P6_2_2_1_1 "Header 1" HDR1X1_SOP 167.089,7.494 r0 top (schematic designator P6)
P6_2_2_1_2 "Header 1" HDR1X1_SOP 182.371,7.494 r0 top (schematic designator P6)
P6_2_2_1_3 "Header 1" HDR1X1_SOP 197.653,7.494 r0 top (schematic designator P6)
P6_2_2_1_4 "Header 1" HDR1X1_SOP 212.935,7.494 r0 top (schematic designator P6)
P6_2_3 "Header 1" HDR1X1_SOP 151.807,53.298 r0 top (schematic designator P6)
P6_2_3_1 "Header 1" HDR1X1_SOP 167.089,53.298 r0 top (schematic designator P6)
P6_2_3_2 "Header 1" HDR1X1_SOP 182.371,53.298 r0 top (schematic designator P6)
P6_2_3_3 "Header 1" HDR1X1_SOP 197.653,53.298 r0 top (schematic designator P6)
P6_2_3_4 "Header 1" HDR1X1_SOP 212.935,53.298 r0 top (schematic designator P6)
R1 "R0805" RES_0805 129.54,75.565 r180 top
R1_1 "R0805" RES_0805 144.822,75.565 r180 top (schematic designator R1)
R1_1_1 "R0805" RES_0805 160.104,75.565 r180 top (schematic designator R1)
R1_1_2 "R0805" RES_0805 175.386,75.565 r180 top (schematic designator R1)
R1_1_3 "R0805" RES_0805 190.668,75.565 r180 top (schematic designator R1)
R1_1_4 "R0805" RES_0805 205.95,75.565 r180 top (schematic designator R1)
R1_2 "R0805" RES_0805 129.54,52.663 r180 top (schematic designator R1)
R1_2_1 "R0805" RES_0805 129.54,29.761 r180 top (schematic designator R1)
R1_2_1_1 "R0805" RES_0805 144.822,29.761 r180 top (schematic designator R1)
R1_2_1_1_1 "R0805" RES_0805 160.104,29.761 r180 top (schematic designator R1)
R1_2_1_1_2 "R0805" RES_0805 175.386,29.761 r180 top (schematic designator R1)
R1_2_1_1_3 "R0805" RES_0805 190.668,29.761 r180 top (schematic designator R1)
R1_2_1_1_4 "R0805" RES_0805 205.95,29.761 r180 top (schematic designator R1)
R1_2_2 "R0805" RES_0805 129.54,6.859 r180 top (schematic designator R1)
R1_2_2_1 "R0805" RES_0805 144.822,6.859 r180 top (schematic designator R1)
R1_2_2_1_1 "R0805" RES_0805 160.104,6.859 r180 top (schematic designator R1)
R1_2_2_1_2 "R0805" RES_0805 175.386,6.859 r180 top (schematic designator R1)
R1_2_2_1_3 "R0805" RES_0805 190.668,6.859 r180 top (schematic designator R1)
R1_2_2_1_4 "R0805" RES_0805 205.95,6.859 r180 top (schematic designator R1)
R1_2_3 "R0805" RES_0805 144.822,52.663 r180 top (schematic designator R1)
R1_2_3_1 "R0805" RES_0805 160.104,52.663 r180 top (schematic designator R1)
R1_2_3_2 "R0805" RES_0805 175.386,52.663 r180 top (schematic designator R1)
R1_2_3_3 "R0805" RES_0805 190.668,52.663 r180 top (schematic designator R1)
R1_2_3_4 "R0805" RES_0805 205.95,52.663 r180 top (schematic designator R1)
R2 "R0805" RES_0805 129.54,78.105 r180 top
R2_1 "R0805" RES_0805 144.822,78.105 r180 top (schematic designator R2)
R2_1_1 "R0805" RES_0805 160.104,78.105 r180 top (schematic designator R2)
R2_1_2 "R0805" RES_0805 175.386,78.105 r180 top (schematic designator R2)
R2_1_3 "R0805" RES_0805 190.668,78.105 r180 top (schematic designator R2)
R2_1_4 "R0805" RES_0805 205.95,78.105 r180 top (schematic designator R2)
R2_2 "R0805" RES_0805 129.54,55.203 r180 top (schematic designator R2)
R2_2_1 "R0805" RES_0805 129.54,32.301 r180 top (schematic designator R2)
R2_2_1_1 "R0805" RES_0805 144.822,32.301 r180 top (schematic designator R2)
R2_2_1_1_1 "R0805" RES_0805 160.104,32.301 r180 top (schematic designator R2)
R2_2_1_1_2 "R0805" RES_0805 175.386,32.301 r180 top (schematic designator R2)
R2_2_1_1_3 "R0805" RES_0805 190.668,32.301 r180 top (schematic designator R2)
R2_2_1_1_4 "R0805" RES_0805 205.95,32.301 r180 top (schematic designator R2)
R2_2_2 "R0805" RES_0805 129.54,9.399 r180 top (schematic designator R2)
R2_2_2_1 "R0805" RES_0805 144.822,9.399 r180 top (schematic designator R2)
R2_2_2_1_1 "R0805" RES_0805 160.104,9.399 r180 top (schematic designator R2)
R2_2_2_1_2 "R0805" RES_0805 175.386,9.399 r180 top (schematic designator R2)
R2_2_2_1_3 "R0805" RES_0805 190.668,9.399 r180 top (schematic designator R2)
R2_2_2_1_4 "R0805" RES_0805 205.95,9.399 r180 top (schematic designator R2)
R2_2_3 "R0805" RES_0805 144.822,55.203 r180 top (schematic designator R2)
R2_2_3_1 "R0805" RES_0805 160.104,55.203 r180 top (schematic designator R2)
R2_2_3_2 "R0805" RES_0805 175.386,55.203 r180 top (schematic designator R2)
R2_2_3_3 "R0805" RES_0805 190.668,55.203 r180 top (schematic designator R2)
R2_2_3_4 "R0805" RES_0805 205.95,55.203 r180 top (schematic designator R2)
R3 "R0805" RES_0805 129.54,80.645 r180 top
R3_1 "R0805" RES_0805 144.822,80.645 r180 top (schematic designator R3)
R3_1_1 "R0805" RES_0805 160.104,80.645 r180 top (schematic designator R3)
R3_1_2 "R0805" RES_0805 175.386,80.645 r180 top (schematic designator R3)
R3_1_3 "R0805" RES_0805 190.668,80.645 r180 top (schematic designator R3)
R3_1_4 "R0805" RES_0805 205.95,80.645 r180 top (schematic designator R3)
R3_2 "R0805" RES_0805 129.54,57.743 r180 top (schematic designator R3)
R3_2_1 "R0805" RES_0805 129.54,34.841 r180 top (schematic designator R3)
R3_2_1_1 "R0805" RES_0805 144.822,34.841 r180 top (schematic designator R3)
R3_2_1_1_1 "R0805" RES_0805 160.104,34.841 r180 top (schematic designator R3)
R3_2_1_1_2 "R0805" RES_0805 175.386,34.841 r180 top (schematic designator R3)
R3_2_1_1_3 "R0805" RES_0805 190.668,34.841 r180 top (schematic designator R3)
R3_2_1_1_4 "R0805" RES_0805 205.95,34.841 r180 top (schematic designator R3)
R3_2_2 "R0805" RES_0805 129.54,11.939 r180 top (schematic designator R3)
R3_2_2_1 "R0805" RES_0805 144.822,11.939 r180 top (schematic designator R3)
R3_2_2_1_1 "R0805" RES_0805 160.104,11.939 r180 top (schematic designator R3)
R3_2_2_1_2 "R0805" RES_0805 175.386,11.939 r180 top (schematic designator R3)
R3_2_2_1_3 "R0805" RES_0805 190.668,11.939 r180 top (schematic designator R3)
R3_2_2_1_4 "R0805" RES_0805 205.95,11.939 r180 top (schematic designator R3)
R3_2_3 "R0805" RES_0805 144.822,57.743 r180 top (schematic designator R3)
R3_2_3_1 "R0805" RES_0805 160.104,57.743 r180 top (schematic designator R3)
R3_2_3_2 "R0805" RES_0805 175.386,57.743 r180 top (schematic designator R3)
R3_2_3_3 "R0805" RES_0805 190.668,57.743 r180 top (schematic designator R3)
R3_2_3_4 "R0805" RES_0805 205.95,57.743 r180 top (schematic designator R3)
R4 "R0805" RES_0805 129.54,83.185 r180 top
R4_1 "R0805" RES_0805 144.822,83.185 r180 top (schematic designator R4)
R4_1_1 "R0805" RES_0805 160.104,83.185 r180 top (schematic designator R4)
R4_1_2 "R0805" RES_0805 175.386,83.185 r180 top (schematic designator R4)
R4_1_3 "R0805" RES_0805 190.668,83.185 r180 top (schematic designator R4)
R4_1_4 "R0805" RES_0805 205.95,83.185 r180 top (schematic designator R4)
R4_2 "R0805" RES_0805 129.54,60.283 r180 top (schematic designator R4)
R4_2_1 "R0805" RES_0805 129.54,37.381 r180 top (schematic designator R4)
R4_2_1_1 "R0805" RES_0805 144.822,37.381 r180 top (schematic designator R4)
R4_2_1_1_1 "R0805" RES_0805 160.104,37.381 r180 top (schematic designator R4)
R4_2_1_1_2 "R0805" RES_0805 175.386,37.381 r180 top (schematic designator R4)
R4_2_1_1_3 "R0805" RES_0805 190.668,37.381 r180 top (schematic designator R4)
R4_2_1_1_4 "R0805" RES_0805 205.95,37.381 r180 top (schematic designator R4)
R4_2_2 "R0805" RES_0805 129.54,14.479 r180 top (schematic designator R4)
R4_2_2_1 "R0805" RES_0805 144.822,14.479 r180 top (schematic designator R4)
R4_2_2_1_1 "R0805" RES_0805 160.104,14.479 r180 top (schematic designator R4)
R4_2_2_1_2 "R0805" RES_0805 175.386,14.479 r180 top (schematic designator R4)
R4_2_2_1_3 "R0805" RES_0805 190.668,14.479 r180 top (schematic designator R4)
R4_2_2_1_4 "R0805" RES_0805 205.95,14.479 r180 top (schematic designator R4)
R4_2_3 "R0805" RES_0805 144.822,60.283 r180 top (schematic designator R4)
R4_2_3_1 "R0805" RES_0805 160.104,60.283 r180 top (schematic designator R4)
R4_2_3_2 "R0805" RES_0805 175.386,60.283 r180 top (schematic designator R4)
R4_2_3_3 "R0805" RES_0805 190.668,60.283 r180 top (schematic designator R4)
R4_2_3_4 "R0805" RES_0805 205.95,60.283 r180 top (schematic designator R4)
R5 "R0805" RES_0805 129.54,85.725 r180 top
R5_1 "R0805" RES_0805 144.822,85.725 r180 top (schematic designator R5)
R5_1_1 "R0805" RES_0805 160.104,85.725 r180 top (schematic designator R5)
R5_1_2 "R0805" RES_0805 175.386,85.725 r180 top (schematic designator R5)
R5_1_3 "R0805" RES_0805 190.668,85.725 r180 top (schematic designator R5)
R5_1_4 "R0805" RES_0805 205.95,85.725 r180 top (schematic designator R5)
R5_2 "R0805" RES_0805 129.54,62.823 r180 top (schematic designator R5)
R5_2_1 "R0805" RES_0805 129.54,39.921 r180 top (schematic designator R5)
R5_2_1_1 "R0805" RES_0805 144.822,39.921 r180 top (schematic designator R5)
R5_2_1_1_1 "R0805" RES_0805 160.104,39.921 r180 top (schematic designator R5)
R5_2_1_1_2 "R0805" RES_0805 175.386,39.921 r180 top (schematic designator R5)
R5_2_1_1_3 "R0805" RES_0805 190.668,39.921 r180 top (schematic designator R5)
R5_2_1_1_4 "R0805" RES_0805 205.95,39.921 r180 top (schematic designator R5)
R5_2_2 "R0805" RES_0805 129.54,17.019 r180 top (schematic designator R5)
R5_2_2_1 "R0805" RES_0805 144.822,17.019 r180 top (schematic designator R5)
R5_2_2_1_1 "R0805" RES_0805 160.104,17.019 r180 top (schematic designator R5)
R5_2_2_1_2 "R0805" RES_0805 175.386,17.019 r180 top (schematic designator R5)
R5_2_2_1_3 "R0805" RES_0805 190.668,17.019 r180 top (schematic designator R5)
R5_2_2_1_4 "R0805" RES_0805 205.95,17.019 r180 top (schematic designator R5)
R5_2_3 "R0805" RES_0805 144.822,62.823 r180 top (schematic designator R5)
R5_2_3_1 "R0805" RES_0805 160.104,62.823 r180 top (schematic designator R5)
R5_2_3_2 "R0805" RES_0805 175.386,62.823 r180 top (schematic designator R5)
R5_2_3_3 "R0805" RES_0805 190.668,62.823 r180 top (schematic designator R5)
R5_2_3_4 "R0805" RES_0805 205.95,62.823 r180 top (schematic designator R5)
R6 "R0805" RES_0805 129.54,88.265 r180 top
R6_1 "R0805" RES_0805 144.822,88.265 r180 top (schematic designator R6)
R6_1_1 "R0805" RES_0805 160.104,88.265 r180 top (schematic designator R6)
R6_1_2 "R0805" RES_0805 175.386,88.265 r180 top (schematic designator R6)
R6_1_3 "R0805" RES_0805 190.668,88.265 r180 top (schematic designator R6)
R6_1_4 "R0805" RES_0805 205.95,88.265 r180 top (schematic designator R6)
R6_2 "R0805" RES_0805 129.54,65.363 r180 top (schematic designator R6)
R6_2_1 "R0805" RES_0805 129.54,42.461 r180 top (schematic designator R6)
R6_2_1_1 "R0805" RES_0805 144.822,42.461 r180 top (schematic designator R6)
R6_2_1_1_1 "R0805" RES_0805 160.104,42.461 r180 top (schematic designator R6)
R6_2_1_1_2 "R0805" RES_0805 175.386,42.461 r180 top (schematic designator R6)
R6_2_1_1_3 "R0805" RES_0805 190.668,42.461 r180 top (schematic designator R6)
R6_2_1_1_4 "R0805" RES_0805 205.95,42.461 r180 top (schematic designator R6)
R6_2_2 "R0805" RES_0805 129.54,19.559 r180 top (schematic designator R6)
R6_2_2_1 "R0805" RES_0805 144.822,19.559 r180 top (schematic designator R6)
R6_2_2_1_1 "R0805" RES_0805 160.104,19.559 r180 top (schematic designator R6)
R6_2_2_1_2 "R0805" RES_0805 175.386,19.559 r180 top (schematic designator R6)
R6_2_2_1_3 "R0805" RES_0805 190.668,19.559 r180 top (schematic designator R6)
R6_2_2_1_4 "R0805" RES_0805 205.95,19.559 r180 top (schematic designator R6)
R6_2_3 "R0805" RES_0805 144.822,65.363 r180 top (schematic designator R6)
R6_2_3_1 "R0805" RES_0805 160.104,65.363 r180 top (schematic designator R6)
R6_2_3_2 "R0805" RES_0805 175.386,65.363 r180 top (schematic designator R6)
R6_2_3_3 "R0805" RES_0805 190.668,65.363 r180 top (schematic designator R6)
R6_2_3_4 "R0805" RES_0805 205.95,65.363 r180 top (schematic designator R6)
R7 "R0805" RES_0805 129.54,90.805 r180 top
R7_1 "R0805" RES_0805 144.822,90.805 r180 top (schematic designator R7)
R7_1_1 "R0805" RES_0805 160.104,90.805 r180 top (schematic designator R7)
R7_1_2 "R0805" RES_0805 175.386,90.805 r180 top (schematic designator R7)
R7_1_3 "R0805" RES_0805 190.668,90.805 r180 top (schematic designator R7)
R7_1_4 "R0805" RES_0805 205.95,90.805 r180 top (schematic designator R7)
R7_2 "R0805" RES_0805 129.54,67.903 r180 top (schematic designator R7)
R7_2_1 "R0805" RES_0805 129.54,45.001 r180 top (schematic designator R7)
R7_2_1_1 "R0805" RES_0805 144.822,45.001 r180 top (schematic designator R7)
R7_2_1_1_1 "R0805" RES_0805 160.104,45.001 r180 top (schematic designator R7)
R7_2_1_1_2 "R0805" RES_0805 175.386,45.001 r180 top (schematic designator R7)
R7_2_1_1_3 "R0805" RES_0805 190.668,45.001 r180 top (schematic designator R7)
R7_2_1_1_4 "R0805" RES_0805 205.95,45.001 r180 top (schematic designator R7)
R7_2_2 "R0805" RES_0805 129.54,22.099 r180 top (schematic designator R7)
R7_2_2_1 "R0805" RES_0805 144.822,22.099 r180 top (schematic designator R7)
R7_2_2_1_1 "R0805" RES_0805 160.104,22.099 r180 top (schematic designator R7)
R7_2_2_1_2 "R0805" RES_0805 175.386,22.099 r180 top (schematic designator R7)
R7_2_2_1_3 "R0805" RES_0805 190.668,22.099 r180 top (schematic designator R7)
R7_2_2_1_4 "R0805" RES_0805 205.95,22.099 r180 top (schematic designator R7)
R7_2_3 "R0805" RES_0805 144.822,67.903 r180 top (schematic designator R7)
R7_2_3_1 "R0805" RES_0805 160.104,67.903 r180 top (schematic designator R7)
R7_2_3_2 "R0805" RES_0805 175.386,67.903 r180 top (schematic designator R7)
R7_2_3_3 "R0805" RES_0805 190.668,67.903 r180 top (schematic designator R7)
R7_2_3_4 "R0805" RES_0805 205.95,67.903 r180 top (schematic designator R7)
R8 "R0805" RES_0805 129.54,93.345 r180 top
R8_1 "R0805" RES_0805 144.822,93.345 r180 top (schematic designator R8)
R8_1_1 "R0805" RES_0805 160.104,93.345 r180 top (schematic designator R8)
R8_1_2 "R0805" RES_0805 175.386,93.345 r180 top (schematic designator R8)
R8_1_3 "R0805" RES_0805 190.668,93.345 r180 top (schematic designator R8)
R8_1_4 "R0805" RES_0805 205.95,93.345 r180 top (schematic designator R8)
R8_2 "R0805" RES_0805 129.54,70.443 r180 top (schematic designator R8)
R8_2_1 "R0805" RES_0805 129.54,47.541 r180 top (schematic designator R8)
R8_2_1_1 "R0805" RES_0805 144.822,47.541 r180 top (schematic designator R8)
R8_2_1_1_1 "R0805" RES_0805 160.104,47.541 r180 top (schematic designator R8)
R8_2_1_1_2 "R0805" RES_0805 175.386,47.541 r180 top (schematic designator R8)
R8_2_1_1_3 "R0805" RES_0805 190.668,47.541 r180 top (schematic designator R8)
R8_2_1_1_4 "R0805" RES_0805 205.95,47.541 r180 top (schematic designator R8)
R8_2_2 "R0805" RES_0805 129.54,24.639 r180 top (schematic designator R8)
R8_2_2_1 "R0805" RES_0805 144.822,24.639 r180 top (schematic designator R8)
R8_2_2_1_1 "R0805" RES_0805 160.104,24.639 r180 top (schematic designator R8)
R8_2_2_1_2 "R0805" RES_0805 175.386,24.639 r180 top (schematic designator R8)
R8_2_2_1_3 "R0805" RES_0805 190.668,24.639 r180 top (schematic designator R8)
R8_2_2_1_4 "R0805" RES_0805 205.95,24.639 r180 top (schematic designator R8)
R8_2_3 "R0805" RES_0805 144.822,70.443 r180 top (schematic designator R8)
R8_2_3_1 "R0805" RES_0805 160.104,70.443 r180 top (schematic designator R8)
R8_2_3_2 "R0805" RES_0805 175.386,70.443 r180 top (schematic designator R8)
R8_2_3_3 "R0805" RES_0805 190.668,70.443 r180 top (schematic designator R8)
R8_2_3_4 "R0805" RES_0805 205.95,70.443 r180 top (schematic designator R8)
U1 "74HC595D,112" SOT109-1_NEX 131.445,84.455 r180 bottom
U1_1 "74HC595D,112" SOT109-1_NEX 146.727,84.455 r180 bottom (schematic designator U1)
U1_1_1 "74HC595D,112" SOT109-1_NEX 162.009,84.455 r180 bottom (schematic designator U1)
U1_1_2 "74HC595D,112" SOT109-1_NEX 177.291,84.455 r180 bottom (schematic designator U1)
U1_1_3 "74HC595D,112" SOT109-1_NEX 192.573,84.455 r180 bottom (schematic designator U1)
U1_1_4 "74HC595D,112" SOT109-1_NEX 207.855,84.455 r180 bottom (schematic designator U1)
U1_2 "74HC595D,112" SOT109-1_NEX 131.445,61.553 r180 bottom (schematic designator U1)
U1_2_1 "74HC595D,112" SOT109-1_NEX 131.445,38.651 r180 bottom (schematic designator U1)
U1_2_1_1 "74HC595D,112" SOT109-1_NEX 146.727,38.651 r180 bottom (schematic designator U1)
U1_2_1_1_1 "74HC595D,112" SOT109-1_NEX 162.009,38.651 r180 bottom (schematic designator U1)
U1_2_1_1_2 "74HC595D,112" SOT109-1_NEX 177.291,38.651 r180 bottom (schematic designator U1)
U1_2_1_1_3 "74HC595D,112" SOT109-1_NEX 192.573,38.651 r180 bottom (schematic designator U1)
U1_2_1_1_4 "74HC595D,112" SOT109-1_NEX 207.855,38.651 r180 bottom (schematic designator U1)
U1_2_2 "74HC595D,112" SOT109-1_NEX 131.445,15.749 r180 bottom (schematic designator U1)
U1_2_2_1 "74HC595D,112" SOT109-1_NEX 146.727,15.749 r180 bottom (schematic designator U1)
U1_2_2_1_1 "74HC595D,112" SOT109-1_NEX 162.009,15.749 r180 bottom (schematic designator U1)
U1_2_2_1_2 "74HC595D,112" SOT109-1_NEX 177.291,15.749 r180 bottom (schematic designator U1)
U1_2_2_1_3 "74HC595D,112" SOT109-1_NEX 192.573,15.749 r180 bottom (schematic designator U1)
U1_2_2_1_4 "74HC595D,112" SOT109-1_NEX 207.855,15.749 r180 bottom (schematic designator U1)
U1_2_3 "74HC595D,112" SOT109-1_NEX 146.727,61.553 r180 bottom (schematic designator U1)
U1_2_3_1 "74HC595D,112" SOT109-1_NEX 162.009,61.553 r180 bottom (schematic designator U1)
U1_2_3_2 "74HC595D,112" SOT109-1_NEX 177.291,61.553 r180 bottom (schematic designator U1)
U1_2_3_3 "74HC595D,112" SOT109-1_NEX 192.573,61.553 r180 bottom (schematic designator U1)
U1_2_3_4 "74HC595D,112" SOT109-1_NEX 207.855,61.553 r180 bottom (schematic designator U1)

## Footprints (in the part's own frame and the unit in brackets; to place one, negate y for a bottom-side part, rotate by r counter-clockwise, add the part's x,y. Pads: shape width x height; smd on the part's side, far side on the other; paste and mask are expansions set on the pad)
HDR1X1_SOP [mil]
  rect 60x120 smd: 1(0,0)
  silkscreen extent -50,-75 50,75
HDR1X5_SOP [mil]
  rect 60x120 smd: 1(0,0) 2(100,0) 3(200,0) 4(300,0) 5(400,0)
  silkscreen extent -50,-75 450,75
LED_0805_RED [mil]
  rrect50% 24x50 smd: 1(-36,0) 2(36,0)
  silkscreen extent -12,-24 12,24, body extent -40,-25 40,25, height 43
RES_0805 [mil]
  rrect50% 24x50 smd: 1(-36,0) 2(36,0)
  silkscreen extent -12,-24 12,24, body extent -39,-25 39,25, height 24
SOT109-1_NEX [mil]
  rect 67x21 smd paste+0 mask+0: 1(-102.5,175) 2(-102.5,125) 3(-102.5,75) 4(-102.5,25) 5(-102.5,-25) 6(-102.5,-75) 7(-102.5,-125) 8(-102.5,-175) 9(102.5,-175) 10(102.5,-125) 11(102.5,-75) 12(102.5,-25) 13(102.5,25) 14(102.5,75) 15(102.5,125) 16(102.5,175)
  silkscreen extent -84,-202 84,202, body extent -122,-197 122,197, height 69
